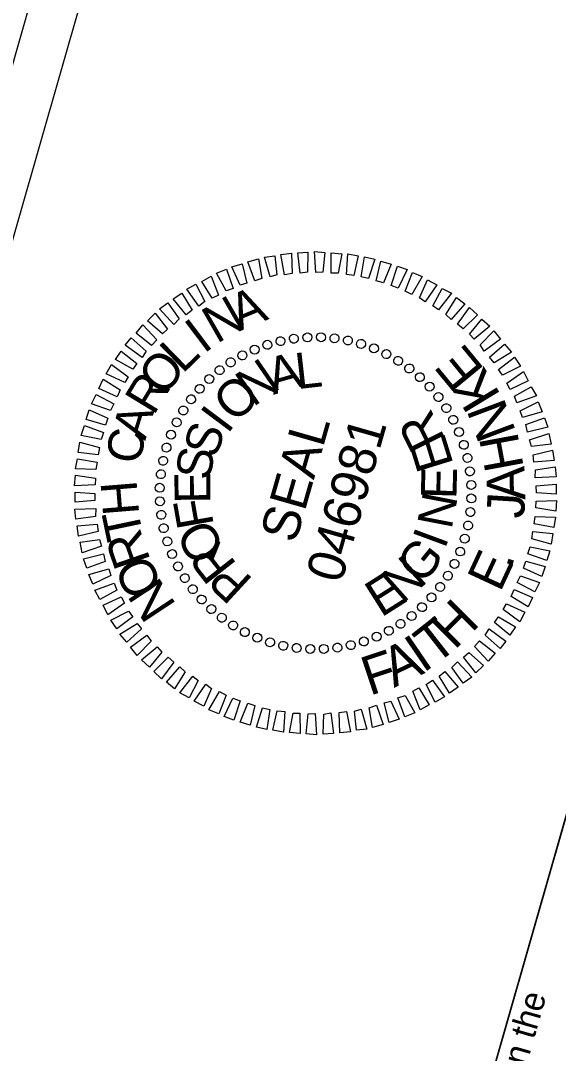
# Model space of a CAD drawing. Extents: x 2096990 to 2098506, y 687712 to 690186.
# Drawn here: x 2097525.6 to 2097612.2, y 689382.1 to 689548.2 of the extents above; entities that cross this region are included whole.
import ezdxf

# ---------------------------------------------------------------- set-up
doc = ezdxf.new("R2010")
doc.units = 0
for name, color, linetype in [('Default', 7, 'Continuous'), ('Sheet Block Title CELL', 7, 'Continuous'), ('Sheet Title CELL', 7, 'Continuous')]:
    doc.layers.add(name, color=color, linetype=linetype)

msp = doc.modelspace()

# ---------------------------------------------------------------- linework, layer by layer
at = {"layer": 'Default'}
for p, q in [((2097567.46, 689496.64), (2097567.46, 689496.64)), ((2097569.61, 689497.06), (2097569.61, 689497.06)), ((2097571.75, 689497.28), (2097571.75, 689497.28)), ((2097573.94, 689497.28), (2097573.94, 689497.28)), ((2097576.16, 689497.06), (2097576.16, 689497.06)), ((2097578.31, 689496.75), (2097578.31, 689496.75)), ((2097580.44, 689496.2), (2097580.44, 689496.2)), ((2097563.29, 689495.33), (2097563.29, 689495.33)), ((2097565.32, 689496.05), (2097565.32, 689496.05)), ((2097582.51, 689495.45), (2097582.51, 689495.45)), ((2097584.48, 689494.52), (2097584.48, 689494.52)), ((2097559.42, 689493.27), (2097559.42, 689493.27)), ((2097561.29, 689494.34), (2097561.29, 689494.34)), ((2097586.38, 689493.51), (2097586.38, 689493.51)), ((2097557.64, 689491.96), (2097557.64, 689491.96)), ((2097588.21, 689492.26), (2097588.21, 689492.26)), ((2097555.95, 689490.57), (2097555.95, 689490.57)), ((2097589.88, 689490.84), (2097589.88, 689490.84)), ((2097554.45, 689488.97), (2097554.45, 689488.97)), ((2097591.48, 689489.34), (2097591.48, 689489.34)), ((2097553.03, 689487.3), (2097553.03, 689487.3)), ((2097592.87, 689487.65), (2097592.87, 689487.65)), ((2097551.78, 689485.47), (2097551.78, 689485.47)), ((2097594.18, 689485.87), (2097594.18, 689485.87)), ((2097550.77, 689483.57), (2097550.77, 689483.57)), ((2097595.25, 689484), (2097595.25, 689484)), ((2097549.84, 689481.6), (2097549.84, 689481.6)), ((2097596.24, 689482), (2097596.24, 689482)), ((2097596.96, 689479.97), (2097596.96, 689479.97)), ((2097549.09, 689479.53), (2097549.09, 689479.53)), ((2097548.54, 689477.4), (2097548.54, 689477.4)), ((2097597.55, 689477.83), (2097597.55, 689477.83)), ((2097548.23, 689475.25), (2097548.23, 689475.25)), ((2097597.97, 689475.68), (2097597.97, 689475.68)), ((2097548.01, 689473.03), (2097548.01, 689473.03)), ((2097598.19, 689473.54), (2097598.19, 689473.54)), ((2097573.1, 689472.19), (2097573.1, 689472.19)), ((2097598.19, 689471.35), (2097598.19, 689471.35)), ((2097548.01, 689470.84), (2097548.01, 689470.84)), ((2097548.23, 689468.7), (2097548.23, 689468.7)), ((2097597.97, 689469.13), (2097597.97, 689469.13)), ((2097548.65, 689466.55), (2097548.65, 689466.55)), ((2097597.66, 689466.98), (2097597.66, 689466.98)), ((2097597.11, 689464.85), (2097597.11, 689464.85)), ((2097549.24, 689464.41), (2097549.24, 689464.41)), ((2097549.96, 689462.38), (2097549.96, 689462.38)), ((2097596.36, 689462.78), (2097596.36, 689462.78)), ((2097550.94, 689460.38), (2097550.94, 689460.38)), ((2097595.43, 689460.8), (2097595.43, 689460.8)), ((2097552.02, 689458.51), (2097552.02, 689458.51)), ((2097594.42, 689458.91), (2097594.42, 689458.91)), ((2097553.33, 689456.73), (2097553.33, 689456.73)), ((2097593.17, 689457.08), (2097593.17, 689457.08)), ((2097554.72, 689455.04), (2097554.72, 689455.04)), ((2097591.75, 689455.41), (2097591.75, 689455.41)), ((2097556.32, 689453.54), (2097556.32, 689453.54)), ((2097590.25, 689453.81), (2097590.25, 689453.81)), ((2097557.99, 689452.12), (2097557.99, 689452.12)), ((2097588.56, 689452.42), (2097588.56, 689452.42)), ((2097559.82, 689450.87), (2097559.82, 689450.87)), ((2097561.71, 689449.86), (2097561.71, 689449.86)), ((2097584.91, 689450.03), (2097584.91, 689450.03)), ((2097586.78, 689451.11), (2097586.78, 689451.11)), ((2097563.69, 689448.93), (2097563.69, 689448.93)), ((2097565.76, 689448.18), (2097565.76, 689448.18)), ((2097580.88, 689448.33), (2097580.88, 689448.33)), ((2097582.91, 689449.05), (2097582.91, 689449.05)), ((2097567.89, 689447.62), (2097567.89, 689447.62)), ((2097570.04, 689447.32), (2097570.04, 689447.32)), ((2097572.26, 689447.1), (2097572.26, 689447.1)), ((2097574.45, 689447.1), (2097574.45, 689447.1)), ((2097576.59, 689447.32), (2097576.59, 689447.32)), ((2097578.74, 689447.74), (2097578.74, 689447.74))]:
    msp.add_line(p, q, dxfattribs=at)
for points in [[(2097563.31, 689506.3), (2097562.21, 689509.37), (2097563.92, 689509.87), (2097564.46, 689506.7)], [(2097565.78, 689506.95), (2097564.87, 689510.12), (2097566.54, 689510.32), (2097566.86, 689507.26)], [(2097568.12, 689507.31), (2097567.49, 689510.56), (2097569.21, 689510.75), (2097569.32, 689507.49)], [(2097570.63, 689507.53), (2097570.22, 689510.82), (2097571.86, 689510.93), (2097571.78, 689507.73)], [(2097573.16, 689507.64), (2097572.93, 689511.03), (2097574.6, 689510.87), (2097574.26, 689507.69)], [(2097575.63, 689507.56), (2097575.58, 689510.85), (2097577.3, 689510.67), (2097576.72, 689507.56)], [(2097578.06, 689507.33), (2097578.28, 689510.65), (2097579.96, 689510.32), (2097579.27, 689507.19)], [(2097580.45, 689506.96), (2097580.96, 689510.19), (2097582.62, 689509.82), (2097581.63, 689506.72)], [(2097582.87, 689506.32), (2097583.62, 689509.48), (2097585.25, 689509.02), (2097584.02, 689505.99)], [(2097558.69, 689504.71), (2097557.16, 689507.54), (2097558.75, 689508.18), (2097559.85, 689505.11)], [(2097560.98, 689505.62), (2097559.64, 689508.55), (2097561.29, 689509.06), (2097562.06, 689505.93)], [(2097585.26, 689505.58), (2097586.25, 689508.68), (2097587.81, 689508.13), (2097586.39, 689505.16)], [(2097556.48, 689503.52), (2097554.81, 689506.24), (2097556.3, 689507.06), (2097557.46, 689504.02)], [(2097587.5, 689504.68), (2097588.67, 689507.68), (2097590.25, 689507.02), (2097588.58, 689504.11)], [(2097589.84, 689503.6), (2097591.08, 689506.47), (2097592.61, 689505.66), (2097590.74, 689502.92)], [(2097554.3, 689502.27), (2097552.37, 689504.96), (2097553.85, 689505.78), (2097555.29, 689502.98)], [(2097591.97, 689502.31), (2097593.45, 689505.11), (2097594.94, 689504.32), (2097592.87, 689501.64)], [(2097552.29, 689500.87), (2097550.16, 689503.41), (2097551.57, 689504.36), (2097553.22, 689501.59)], [(2097594.07, 689500.93), (2097595.79, 689503.66), (2097597.1, 689502.61), (2097594.93, 689500.11)], [(2097550.28, 689499.32), (2097547.98, 689501.8), (2097549.34, 689502.76), (2097551.16, 689500.21)], [(2097595.91, 689499.36), (2097597.87, 689502.03), (2097599.15, 689500.88), (2097596.83, 689498.58)], [(2097548.45, 689497.81), (2097546.08, 689499.89), (2097547.31, 689501.1), (2097549.29, 689498.56)], [(2097597.84, 689497.77), (2097599.83, 689500.16), (2097601.11, 689499.02), (2097598.59, 689496.93)], [(2097546.71, 689495.92), (2097544.22, 689497.93), (2097545.32, 689499.23), (2097547.54, 689496.82)], [(2097599.58, 689496.02), (2097601.79, 689498.3), (2097602.86, 689496.95), (2097600.23, 689495)], [(2097545.18, 689494.02), (2097542.47, 689495.99), (2097543.43, 689497.17), (2097545.83, 689495.03)], [(2097601.09, 689494.03), (2097603.47, 689496.16), (2097604.6, 689494.84), (2097601.83, 689493.14)], [(2097543.69, 689492.1), (2097540.92, 689493.67), (2097541.83, 689495.03), (2097544.32, 689493.01)], [(2097542.41, 689489.97), (2097539.42, 689491.35), (2097540.27, 689492.87), (2097542.94, 689490.91)], [(2097602.5, 689492.06), (2097605.09, 689494.03), (2097606.04, 689492.61), (2097603.18, 689491.14)], [(2097603.85, 689489.86), (2097606.52, 689491.75), (2097607.28, 689490.23), (2097604.4, 689488.87)], [(2097541.18, 689487.67), (2097538.23, 689488.99), (2097538.92, 689490.5), (2097541.65, 689488.78)], [(2097540.13, 689485.47), (2097537.06, 689486.56), (2097537.81, 689488.07), (2097540.66, 689486.57)], [(2097605.08, 689487.79), (2097607.8, 689489.3), (2097608.62, 689487.82), (2097605.49, 689486.69)], [(2097606.02, 689485.44), (2097608.92, 689486.85), (2097609.55, 689485.26), (2097606.38, 689484.35)], [(2097539.3, 689483.11), (2097536.18, 689484.01), (2097536.68, 689485.58), (2097539.68, 689484.25)], [(2097538.59, 689480.82), (2097535.4, 689481.47), (2097535.9, 689483.05), (2097538.97, 689481.96)], [(2097606.94, 689483.2), (2097609.9, 689484.28), (2097610.45, 689482.77), (2097607.21, 689481.98)], [(2097607.53, 689480.74), (2097610.64, 689481.78), (2097610.98, 689480.07), (2097607.85, 689479.66)], [(2097538.14, 689478.35), (2097534.92, 689478.7), (2097535.19, 689480.39), (2097538.33, 689479.54)], [(2097608.1, 689478.35), (2097611.23, 689479.11), (2097611.47, 689477.43), (2097608.23, 689477.16)], [(2097537.77, 689475.96), (2097534.48, 689476.07), (2097534.79, 689477.7), (2097537.96, 689477.15)], [(2097608.5, 689475.94), (2097611.65, 689476.39), (2097611.81, 689474.79), (2097608.44, 689474.66)], [(2097537.64, 689473.5), (2097534.32, 689473.36), (2097534.45, 689475.09), (2097537.69, 689474.58)], [(2097608.59, 689473.37), (2097611.79, 689473.65), (2097611.8, 689472.03), (2097608.64, 689472.26)], [(2097537.6, 689471.01), (2097534.4, 689470.73), (2097534.4, 689472.35), (2097537.56, 689472.12)], [(2097537.7, 689468.44), (2097534.55, 689467.98), (2097534.39, 689469.59), (2097537.76, 689469.72)], [(2097608.56, 689470.88), (2097611.88, 689471.02), (2097611.74, 689469.29), (2097608.51, 689469.8)], [(2097608.43, 689468.42), (2097611.72, 689468.31), (2097611.41, 689466.68), (2097608.24, 689467.23)], [(2097538.1, 689466.03), (2097534.97, 689465.26), (2097534.73, 689466.95), (2097537.97, 689467.21)], [(2097538.67, 689463.64), (2097535.56, 689462.6), (2097535.22, 689464.31), (2097538.35, 689464.71)], [(2097608.05, 689466.03), (2097611.28, 689465.68), (2097611.01, 689463.99), (2097607.87, 689464.84)], [(2097607.61, 689463.56), (2097610.8, 689462.91), (2097610.3, 689461.33), (2097607.23, 689462.42)], [(2097539.26, 689461.18), (2097536.3, 689460.1), (2097535.75, 689461.61), (2097538.99, 689462.4)], [(2097540.18, 689458.94), (2097537.28, 689457.53), (2097536.64, 689459.12), (2097539.82, 689460.03)], [(2097606.9, 689461.27), (2097610.02, 689460.37), (2097609.52, 689458.8), (2097606.52, 689460.13)], [(2097606.07, 689458.9), (2097609.14, 689457.82), (2097608.39, 689456.31), (2097605.54, 689457.81)], [(2097541.12, 689456.59), (2097538.4, 689455.08), (2097537.58, 689456.56), (2097540.71, 689457.69)], [(2097605.02, 689456.71), (2097607.97, 689455.39), (2097607.28, 689453.88), (2097604.55, 689455.59)], [(2097542.35, 689454.52), (2097539.68, 689452.63), (2097538.92, 689454.15), (2097541.8, 689455.51)], [(2097543.69, 689452.31), (2097541.1, 689450.35), (2097540.16, 689451.77), (2097543.02, 689453.23)], [(2097603.79, 689454.41), (2097606.78, 689453.03), (2097605.93, 689451.51), (2097603.26, 689453.47)], [(2097602.51, 689452.28), (2097605.28, 689450.7), (2097604.37, 689449.35), (2097601.88, 689451.36)], [(2097545.11, 689450.35), (2097542.73, 689448.22), (2097541.6, 689449.53), (2097544.37, 689451.24)], [(2097601.02, 689450.36), (2097603.73, 689448.39), (2097602.77, 689447.21), (2097600.37, 689449.35)], [(2097546.62, 689448.36), (2097544.41, 689446.08), (2097543.33, 689447.42), (2097545.97, 689449.37)], [(2097599.49, 689448.46), (2097601.98, 689446.45), (2097600.88, 689445.15), (2097598.66, 689447.55)], [(2097548.35, 689446.61), (2097546.37, 689444.22), (2097545.09, 689445.36), (2097547.61, 689447.45)], [(2097597.75, 689446.57), (2097600.12, 689444.48), (2097598.89, 689443.28), (2097596.91, 689445.82)], [(2097550.29, 689445.02), (2097548.33, 689442.35), (2097547.05, 689443.5), (2097549.37, 689445.8)], [(2097595.92, 689445.06), (2097598.22, 689442.58), (2097596.85, 689441.62), (2097595.04, 689444.17)], [(2097552.13, 689443.45), (2097550.41, 689440.72), (2097549.1, 689441.77), (2097551.27, 689444.27)], [(2097593.91, 689443.5), (2097596.04, 689440.97), (2097594.63, 689440.02), (2097592.97, 689442.78)], [(2097554.23, 689442.07), (2097552.75, 689439.27), (2097551.26, 689440.06), (2097553.33, 689442.74)], [(2097556.36, 689440.78), (2097555.12, 689437.91), (2097553.58, 689438.72), (2097555.46, 689441.46)], [(2097591.9, 689442.1), (2097593.83, 689439.42), (2097592.35, 689438.59), (2097590.91, 689441.4)], [(2097558.7, 689439.7), (2097557.53, 689436.7), (2097555.95, 689437.36), (2097557.62, 689440.27)], [(2097589.72, 689440.86), (2097591.39, 689438.14), (2097589.9, 689437.32), (2097588.74, 689440.35)], [(2097560.94, 689438.8), (2097559.95, 689435.7), (2097558.39, 689436.25), (2097559.81, 689439.22)], [(2097563.33, 689438.06), (2097562.58, 689434.89), (2097560.95, 689435.36), (2097562.18, 689438.39)], [(2097582.89, 689438.08), (2097583.99, 689435.01), (2097582.28, 689434.51), (2097581.74, 689437.68)], [(2097585.22, 689438.76), (2097586.56, 689435.83), (2097584.91, 689435.32), (2097584.14, 689438.45)], [(2097587.51, 689439.67), (2097589.04, 689436.84), (2097587.45, 689436.2), (2097586.35, 689439.27)], [(2097565.75, 689437.42), (2097565.24, 689434.19), (2097563.58, 689434.56), (2097564.57, 689437.65)], [(2097568.14, 689437.05), (2097567.92, 689433.73), (2097566.24, 689434.05), (2097566.93, 689437.19)], [(2097570.57, 689436.82), (2097570.61, 689433.53), (2097568.9, 689433.71), (2097569.48, 689436.82)], [(2097573.04, 689436.74), (2097573.27, 689433.34), (2097571.6, 689433.51), (2097571.93, 689436.69)], [(2097575.57, 689436.85), (2097575.98, 689433.56), (2097574.34, 689433.45), (2097574.42, 689436.65)], [(2097578.08, 689437.06), (2097578.71, 689433.81), (2097576.99, 689433.63), (2097576.88, 689436.89)], [(2097580.42, 689437.43), (2097581.33, 689434.26), (2097579.66, 689434.06), (2097579.34, 689437.12)]]:
    msp.add_lwpolyline(points, close=True, dxfattribs=at)
for centre, major_axis in [((2097571.78, 689497.23), (-0.038, 0.719)), ((2097573.96, 689497.25), (0.025, 0.72)), ((2097576.14, 689497.08), (0.087, 0.715)), ((2097565.34, 689496.04), (-0.223, 0.685)), ((2097567.45, 689496.62), (-0.162, 0.701)), ((2097569.6, 689497.02), (-0.101, 0.713)), ((2097578.3, 689496.72), (0.149, 0.704)), ((2097580.42, 689496.18), (0.21, 0.689)), ((2097582.48, 689495.45), (0.269, 0.668)), ((2097561.32, 689494.33), (-0.338, 0.636)), ((2097563.29, 689495.27), (-0.282, 0.663)), ((2097584.48, 689494.54), (0.327, 0.642)), ((2097559.43, 689493.22), (-0.392, 0.604)), ((2097586.38, 689493.46), (0.381, 0.611)), ((2097588.18, 689492.23), (0.433, 0.575)), ((2097555.99, 689490.52), (-0.491, 0.526)), ((2097557.65, 689491.95), (-0.444, 0.567)), ((2097589.87, 689490.83), (0.482, 0.535)), ((2097554.45, 689488.96), (-0.535, 0.482)), ((2097591.43, 689489.3), (0.526, 0.491)), ((2097553.06, 689487.27), (-0.575, 0.433)), ((2097592.86, 689487.64), (0.567, 0.444)), ((2097551.82, 689485.47), (-0.611, 0.381)), ((2097594.13, 689485.86), (0.604, 0.392)), ((2097595.24, 689483.97), (0.636, 0.338)), ((2097550.75, 689483.57), (-0.642, 0.327)), ((2097549.84, 689481.57), (-0.668, 0.269)), ((2097596.18, 689482), (0.663, 0.282)), ((2097549.11, 689479.51), (-0.689, 0.21)), ((2097596.95, 689479.95), (0.685, 0.223)), ((2097548.57, 689477.39), (-0.704, 0.149)), ((2097597.53, 689477.84), (0.701, 0.162)), ((2097597.93, 689475.69), (0.713, 0.101)), ((2097548.21, 689475.23), (-0.715, 0.087)), ((2097548.03, 689473.05), (-0.72, 0.025)), ((2097598.14, 689473.51), (0.719, 0.038)), ((2097548.05, 689470.87), (-0.719, -0.038)), ((2097598.16, 689471.33), (0.72, -0.025)), ((2097597.99, 689469.14), (0.715, -0.087)), ((2097548.27, 689468.69), (-0.713, -0.101)), ((2097548.66, 689466.54), (-0.701, -0.162)), ((2097597.63, 689466.99), (0.704, -0.149)), ((2097549.25, 689464.43), (-0.685, -0.223)), ((2097597.09, 689464.87), (0.689, -0.21)), ((2097550.02, 689462.38), (-0.663, -0.282)), ((2097596.36, 689462.8), (0.668, -0.269)), ((2097595.45, 689460.81), (0.642, -0.327)), ((2097550.96, 689460.4), (-0.636, -0.338)), ((2097594.37, 689458.91), (0.611, -0.381)), ((2097552.07, 689458.52), (-0.604, -0.392)), ((2097553.34, 689456.74), (-0.567, -0.444)), ((2097593.14, 689457.1), (0.575, -0.433)), ((2097554.76, 689455.08), (-0.526, -0.491)), ((2097590.21, 689453.85), (0.491, -0.526)), ((2097591.75, 689455.42), (0.535, -0.482)), ((2097556.33, 689453.54), (-0.482, -0.535)), ((2097588.55, 689452.43), (0.444, -0.567)), ((2097558.02, 689452.15), (-0.433, -0.575)), ((2097559.82, 689450.91), (-0.381, -0.611)), ((2097586.77, 689451.16), (0.392, -0.604)), ((2097561.72, 689449.84), (-0.327, -0.642)), ((2097563.71, 689448.93), (-0.269, -0.668)), ((2097582.91, 689449.11), (0.282, -0.663)), ((2097584.88, 689450.05), (0.338, -0.636)), ((2097565.78, 689448.2), (-0.21, -0.689)), ((2097567.9, 689447.65), (-0.149, -0.704)), ((2097570.05, 689447.29), (-0.087, -0.715)), ((2097576.6, 689447.35), (0.101, -0.713)), ((2097578.75, 689447.75), (0.162, -0.701)), ((2097580.86, 689448.34), (0.223, -0.685)), ((2097572.24, 689447.12), (-0.025, -0.72)), ((2097574.42, 689447.14), (0.038, -0.719))]:
    msp.add_ellipse(centre, major_axis=major_axis, ratio=0.999708, dxfattribs=at)
at = {"layer": 'Sheet Block Title CELL'}
msp.add_lwpolyline([(2097594.87, 689355.54), (2097649.93, 689547.88), (2097675.17, 689540.65), (2097620.12, 689348.32)], close=True, dxfattribs=at)
at = {"layer": 'Sheet Title CELL'}
for p, q in [((2097488.06, 689386.12), (2097545.74, 689587.61)), ((2097489.7, 689420.02), (2097535.64, 689580.51)), ((2097652.55, 689557.03), (2097594.87, 689355.54))]:
    msp.add_line(p, q, dxfattribs=at)

# ---------------------------------------------------------------- texts
at = {"layer": 'Default'}
for s, height, rotation, p in [('A', 5.93, 22.643, (2097560.83, 689498.17)), ('N', 5.96, 29.8448, (2097557.18, 689496.15)), ('I', 5.95, 37.046, (2097555.1, 689494.51)), ('L', 5.91, 44.2468, (2097551.67, 689491.27)), ('O', 5.83, 51.4471, (2097548.68, 689487.55)), ('L', 5.78, 6.4267, (2097570.13, 689488.9)), ('E', 6.27, 129.5189, (2097600.41, 689492.04)), ('N', 5.96, 34.5025, (2097563, 689485.95)), ('A', 5.87, 15.7862, (2097566.28, 689487.98)), ('R', 5.74, 58.647, (2097547.04, 689484.54)), ('K', 6.33, 121.235, (2097602.99, 689487.9)), ('O', 5.91, 43.8594, (2097560.15, 689483.28)), ('N', 6.33, 110.5092, (2097605.39, 689482.06)), ('A', 5.64, 73.0462, (2097545.69, 689480.55)), ('I', 5.81, 53.2155, (2097558.93, 689481.55)), ('R', 5.96, 116.5073, (2097594.04, 689480.86)), ('S', 5.64, 71.9263, (2097557.07, 689477.61)), ('SEAL', 5.998, 74.0259, (2097569.86, 689463.96)), ('046981', 5.998, 74.0259, (2097577.23, 689457.51)), ('C', 5.66, 80.2458, (2097544.89, 689476.67)), ('E', 5.93, 107.15, (2097595.33, 689476.8)), ('H', 6.25, 100.5252, (2097606.61, 689476.32)), ('S', 5.66, 81.2815, (2097556.13, 689474.13)), ('A', 6.14, 91.6849, (2097606.85, 689471.12)), ('E', 5.76, 90.637, (2097556.19, 689470.53)), ('E', 5.73, 88.4377, (2097595.74, 689471.17)), ('H', 5.81, 94.6454, (2097544.73, 689468.82)), ('N', 5.65, 79.0823, (2097594.96, 689466.24)), ('J', 6.07, 86.427, (2097606.61, 689468.03)), ('F', 5.87, 99.9929, (2097556.75, 689467.04)), ('T', 5.89, 101.8457, (2097545.42, 689465.24)), ('R', 5.94, 109.0464, (2097546.6, 689461.36)), ('O', 5.96, 118.7071, (2097558.68, 689463.06)), ('I', 5.65, 69.7271, (2097593.89, 689463.06)), ('R', 5.91, 128.0655, (2097560.55, 689460.7)), ('G', 5.84, 51.0161, (2097590.26, 689457.29)), ('E', 6.04, 65.0836, (2097602.79, 689456.12)), ('O', 5.96, 116.2476, (2097548.63, 689457.19)), ('N', 5.93, 41.6598, (2097587.05, 689454.26)), ('.', 6, 72.1929, (2097604.55, 689459.92)), ('E', 5.96, 32.3028, (2097583.63, 689452.12)), ('N', 5.94, 123.4494, (2097550.78, 689454.19)), ('P', 5.82, 137.4248, (2097563.19, 689458.28)), ('H', 6.28, 44.8992, (2097595.43, 689446.86)), ('T', 6.33, 38.099, (2097592.27, 689444.4)), ('I', 6.34, 34.297, (2097590.38, 689443.19)), ('F', 6.27, 18.4401, (2097581.8, 689439.57)), ('A', 6.32, 25.4567, (2097585.72, 689440.87))]:
    msp.add_text(s, height=height, rotation=rotation, dxfattribs=at).set_placement(p)
at = {"layer": 'Sheet Block Title CELL'}
msp.add_text('Prepared in the ', height=4.0012, rotation=74.0259, dxfattribs=at).set_placement((2097600.2, 689356.23))

doc.saveas('drawing.dxf')
